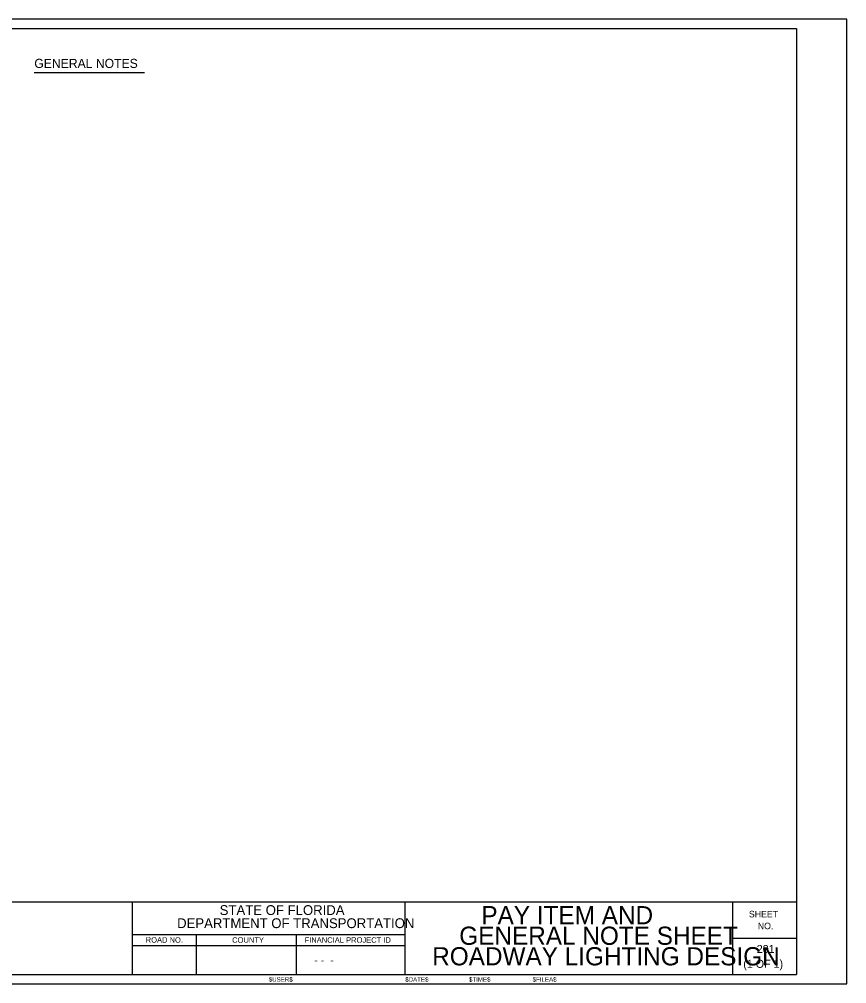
# Model space of a CAD drawing. Extents: x 17892376 to 17893036, y 17895402 to 17895826.
# Drawn here: x 17892672.5 to 17893036.2, y 17895401.7 to 17895825.7 of the extents above; entities that cross this region are included whole.
import ezdxf

# ---------------------------------------------------------------- set-up
doc = ezdxf.new("R2010")
doc.units = 0
for name, color, linetype in [('PlotBorder_dp', 7, 'Continuous'), ('SheetBorder_dp', 7, 'Continuous'), ('SheetLines_dp', 7, 'Continuous'), ('TextLabel', 7, 'Continuous'), ('TextMinor', 7, 'Continuous'), ('TextMisc', 7, 'Continuous')]:
    doc.layers.add(name, color=color, linetype=linetype)

msp = doc.modelspace()

# ---------------------------------------------------------------- linework, layer by layer
at = {"layer": 'PlotBorder_dp'}
msp.add_lwpolyline([(17892376.17, 17895401.68), (17893036.17, 17895401.68), (17893036.17, 17895825.68), (17892376.17, 17895825.68)], close=True, dxfattribs=at)
at = {"layer": 'SheetBorder_dp'}
for p, q in [((17892398.17, 17895821.68), (17893014.17, 17895821.68)), ((17893014.17, 17895821.68), (17893014.17, 17895405.68)), ((17892398.17, 17895437.68), (17893014.17, 17895437.68)), ((17892398.17, 17895405.68), (17893014.17, 17895405.68))]:
    msp.add_line(p, q, dxfattribs=at)
at = {"layer": 'SheetLines_dp'}
for p, q in [((17892722.17, 17895437.68), (17892722.17, 17895405.68)), ((17892842.17, 17895405.68), (17892842.17, 17895437.68)), ((17892986.17, 17895405.68), (17892986.17, 17895437.68)), ((17892722.17, 17895423.28), (17892842.17, 17895423.28)), ((17892750.17, 17895423.28), (17892750.17, 17895405.68)), ((17892794.17, 17895423.28), (17892794.17, 17895405.68)), ((17892986.17, 17895421.68), (17893014.17, 17895421.68)), ((17892722.17, 17895418.48), (17892842.17, 17895418.48))]:
    msp.add_line(p, q, dxfattribs=at)
at = {"layer": 'TextLabel'}
msp.add_line((17892679.09, 17895802.28), (17892727.54, 17895802.28), dxfattribs=at)

# ---------------------------------------------------------------- texts
msp.add_text('GENERAL NOTES', height=4, rotation=360, dxfattribs=at).set_placement((17892679.09, 17895804.28))
for s, p in [('201', (17892996.64, 17895415.18)), ('(1 OF 1)', (17892990.71, 17895408.66))]:
    msp.add_text(s, height=3.52, dxfattribs=at).set_placement(p)
at = {"layer": 'TextMinor'}
msp.add_text('$USER$', height=1.96, dxfattribs=at).set_placement((17892782.13, 17895402.56))
for s, p in [('$DATE$', (17892842.13, 17895402.56)), ('$TIME$', (17892870.13, 17895402.56)), ('$FILEA$', (17892898.13, 17895402.56))]:
    msp.add_text(s, height=1.96, rotation=360, dxfattribs=at).set_placement(p)
at = {"layer": 'TextMisc'}
for s, height, p in [('STATE OF FLORIDA', 4.32, (17892760.57, 17895431.88)), ('      PAY ITEM AND      ', 7.9999, (17892857.76, 17895427.8)), ('DEPARTMENT OF TRANSPORTATION', 4.32, (17892741.85, 17895426.12)), ('GENERAL NOTE SHEET', 7.9999, (17892865.87, 17895418.77)), ('ROAD NO.', 2.4, (17892728.05, 17895419.72)), ('COUNTY', 2.4, (17892766.05, 17895419.68)), ('FINANCIAL PROJECT ID', 2.4, (17892797.89, 17895419.68)), ('ROADWAY LIGHTING DESIGN', 7.9999, (17892853.98, 17895409.74)), ('      - -  -  ', 3.5201, (17892794.25, 17895410.32))]:
    msp.add_text(s, height=height, dxfattribs=at).set_placement(p)
for s, p in [('SHEET', (17892993.17, 17895430.84)), ('NO.', (17892997.09, 17895425.64))]:
    msp.add_text(s, height=2.88, rotation=359.8607, dxfattribs=at).set_placement(p)

doc.saveas('drawing.dxf')
